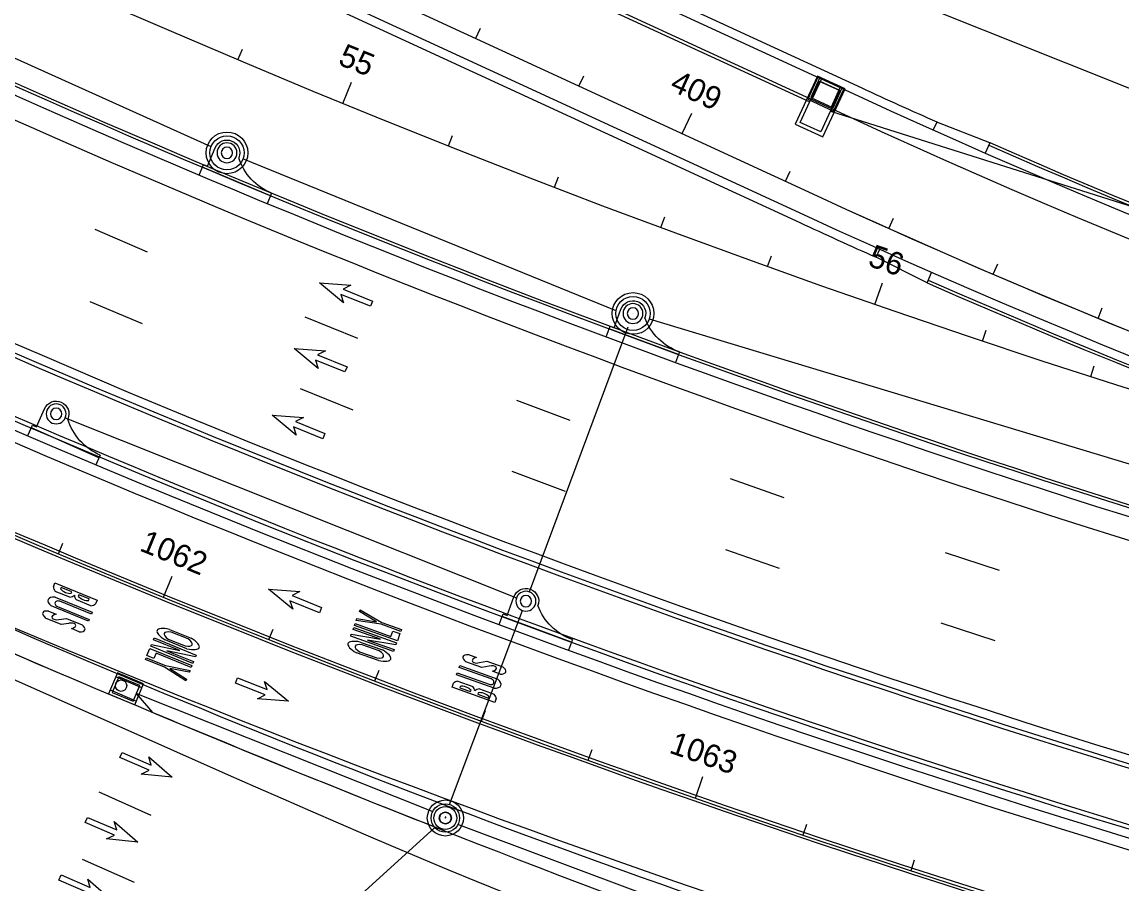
# Model space of a CAD drawing. Extents: x 468143 to 491361, y 1438528 to 1468730.
# Drawn here: x 488398.6 to 488592, y 1466773.1 to 1466924.6 of the extents above; entities that cross this region are included whole.
import ezdxf

# ---------------------------------------------------------------- set-up
doc = ezdxf.new("R2010")
doc.units = 0
doc.layers.add('Default', color=7, linetype='Continuous')
doc.layers.add('Xreference_dp', color=7, linetype='Continuous')

# ---------------------------------------------------------------- blocks, each defined once
blk = doc.blocks.new('POINT_DISPLAY')
at = {"layer": 'Default'}
blk.add_line((0, 0), (0, 0), dxfattribs=at)
blk = doc.blocks.new('InltCurb1_35')
at = {"layer": 'Default'}
for p, q in [((2.25, 2), (2.25, 5.5)), ((-10, 2), (-10, 0)), ((3, 2), (2.25, 2)), ((3, 0), (3, 2)), ((-10, 1.5), (3, 1.5))]:
    blk.add_line(p, q, dxfattribs=at)
for radius in [1.75, 1]:
    blk.add_circle((0, 5.5), radius, dxfattribs=at)
for centre, radius, start, end in [((0, 5.5), 2.25, 0, 180), ((-9.85, 12), 10, 269.1432, 319.4677)]:
    blk.add_arc(centre, radius, start, end, dxfattribs=at)
for p in [(0, 7.75), (-1.6, 6.2), (-1.22, 6.76), (-0.66, 7.12), (0, 7.25), (0, 7.25), (0.7, 7.1), (1.26, 6.72), (1.62, 6.16), (-1.75, 5.5), (-1.75, 5.5), (-1.62, 4.84), (-1.26, 4.28), (-0.7, 3.9), (0, 5.5), (0, 5.5), (0.66, 3.88), (1.22, 4.24), (1.6, 4.8), (1.75, 5.5), (1.75, 5.5), (0, 3.75), (0, 3.75), (0, 0), (0, 0)]:
    blk.add_blockref('POINT_DISPLAY', p, dxfattribs=at)
blk = doc.blocks.new('MHCover2')
at = {"layer": 'Default'}
for radius in [2, 1.06, 1]:
    blk.add_circle((0, 0), radius, dxfattribs=at)
for p in [(0, 2.5), (0, 2), (0, 2), (-2, 0), (-2, 0), (-1.83, 0.81), (-1.39, 1.43), (-0.75, 1.85), (0, 0), (0, 0), (0, 0), (0.81, 1.83), (1.43, 1.39), (1.85, 0.75), (2, 0), (2, 0), (-1.85, -0.75), (-1.43, -1.39), (-0.81, -1.83), (0.75, -1.85), (1.39, -1.43), (1.83, -0.81), (0, -2), (0, -2), (0, -2.5)]:
    blk.add_blockref('POINT_DISPLAY', p, dxfattribs=at)
blk = doc.blocks.new('InltCurb7_40')
at = {"layer": 'Default'}
for p, q in [((2.5, 4), (-2.5, 4)), ((-2.5, 4), (-2.5, 0)), ((2.5, 0), (2.5, 4)), ((2.5, 3.25), (-2.5, 3.25)), ((-2.5, 0.75), (2.5, 0.75)), ((-2.5, 0), (2.5, 0))]:
    blk.add_line(p, q, dxfattribs=at)
blk.add_lwpolyline([(-2, 0.5), (2, 0.5), (2, 3.5), (-2, 3.5)], close=True, dxfattribs=at)
blk.add_circle((-1.04, 2.19), 1, dxfattribs=at)
for p in [(0, 4), (-2, 3.5), (-2, 2), (-2, 2), (0, 3.5), (0, 3.5), (0, 2), (0, 2), (2, 3.5), (2, 2), (2, 2), (-2, 0.5), (0, 0.5), (0, 0.5), (0, 0), (0, 0), (2, 0.5)]:
    blk.add_blockref('POINT_DISPLAY', p, dxfattribs=at)
blk = doc.blocks.new('JBottom50Dia')
at = {"layer": 'Default'}
for radius in [3.17, 2.5, 2.5]:
    blk.add_circle((0, 0), radius, dxfattribs=at)
for p in [(-0.94, 2.32), (0, 2.5), (0, 2.5), (0, 2.5), (1.01, 2.29), (-2.29, 1.01), (-1.74, 1.79), (0, 0), (0, 0), (0, 0), (1.79, 1.74), (2.32, 0.94), (2.5, 0), (2.5, 0), (-2.5, 0), (-2.5, 0), (-2.32, -0.94), (-1.79, -1.74), (1.74, -1.79), (2.29, -1.01), (-1.01, -2.29), (0, -2.5), (0, -2.5), (0, -2.5), (0.94, -2.32)]:
    blk.add_blockref('POINT_DISPLAY', p, dxfattribs=at)
blk = doc.blocks.new('JBottom60Dia')
at = {"layer": 'Default'}
for radius in [3.67, 3, 3]:
    blk.add_circle((0, 0), radius, dxfattribs=at)
for p in [(-2.09, 2.15), (-1.13, 2.78), (0, 3), (0, 3), (0, 3), (1.21, 2.75), (2.15, 2.09), (-2.75, 1.21), (0, 0), (0, 0), (0, 0), (2.78, 1.13), (3, 0), (3, 0), (-3, 0), (-3, 0), (-2.78, -1.13), (2.75, -1.21), (-2.15, -2.09), (-1.21, -2.75), (0, -3), (0, -3), (0, -3), (1.13, -2.78), (2.09, -2.15)]:
    blk.add_blockref('POINT_DISPLAY', p, dxfattribs=at)
blk = doc.blocks.new('JBottom40x80')
at = {"layer": 'Default'}
for p, q in [((2.67, 4.67), (-2.67, 4.67)), ((-2.67, 4.67), (-2.67, -4.67)), ((-2, -4), (-2, 4)), ((-2, 4), (2, 4)), ((2, 4), (2, -4)), ((2.67, -4.67), (2.67, 4.67)), ((-2.67, -4.67), (2.67, -4.67)), ((2, -4), (-2, -4))]:
    blk.add_line(p, q, dxfattribs=at)
for p in [(-2, 4), (0, 4), (0, 4), (0, 4), (2, 4), (-2, 0), (-2, 0), (0, 0), (0, 0), (0, 0), (2, 0), (2, 0), (-2, -4), (0, -4), (0, -4), (0, -4), (2, -4)]:
    blk.add_blockref('POINT_DISPLAY', p, dxfattribs=at)
blk = doc.blocks.new('DAMerge_2')
at = {"layer": 'Default'}
blk.add_lwpolyline([(0.71, -4.09), (0, -3.39), (3.95, 0.56), (2.42, 0.68), (7.31, 3.21), (4.77, -1.68), (4.66, -0.15), (0.71, -4.09)], dxfattribs=at)
blk = doc.blocks.new('BUS_7')
at = {"layer": 'Default'}
for p, q in [((0, 2.46), (0, 3.17)), ((0, 3.17), (8, 3.17)), ((3.33, 2.83), (1.33, 2.83)), ((1.33, 2.83), (1.33, 2.58)), ((3.33, 2.58), (3.33, 2.83)), ((6.67, 2.83), (4.67, 2.83)), ((4.67, 2.83), (4.67, 2.58)), ((6.67, 2.58), (6.67, 2.83)), ((8, 3.17), (8, 2.46)), ((3.38, 1.83), (0.62, 1.83)), ((0.97, 0.86), (8, 0.86)), ((8, 0.5), (2, 0.5)), ((7.38, 1.83), (4.62, 1.83)), ((8, 0.86), (8, 0.5)), ((0.8, -1.83), (2.26, -1.83)), ((8, -0.83), (0.89, -0.83)), ((2, -0.5), (8, -0.5)), ((3.08, -2.5), (4.23, -1.83)), ((4.23, -1.83), (7.2, -1.83)), ((8, -0.5), (8, -0.83)), ((3.77, -3.17), (0.8, -3.17)), ((4.93, -2.5), (3.77, -3.17)), ((7.2, -3.17), (5.74, -3.17))]:
    blk.add_line(p, q, dxfattribs=at)
for centre, major_axis, ratio, start_param, end_param in [((2, 2.83), (-2.08, 0), 0.64, 0.283794, 0.848062), ((2.33, 2.83), (-1.17, 0), 0.428571, 0.5411, 2.600493), ((2, 2.83), (-2.08, 0), 0.64, 2.293531, 2.857799), ((6, 2.83), (2.08, 0), 0.64, 3.425387, 3.989655), ((5.67, 2.83), (1.17, 0), 0.428571, 3.682692, 5.742086), ((6, 2.83), (2.08, 0), 0.64, 5.435123, 5.999391), ((2, 0), (2, 0), 0.5, 2.110653, 4.126703), ((2, 0), (0.667, 0), 0.75, 1.570796, 4.712389), ((2, -2.5), (-2, 0), 0.416667, 5.35589, 7.210481), ((2.67, -2.17), (-0.877, -0.48), 0.5, 4.914869, 8.056461), ((6, -2.5), (2, 0), 0.416667, 5.35589, 7.210481), ((5.33, -2.83), (-0.869, -0.495), 0.5, 1.760499, 4.902092)]:
    blk.add_ellipse(centre, major_axis=major_axis, ratio=ratio, start_param=start_param, end_param=end_param, dxfattribs=at)
blk = doc.blocks.new('BikeONLY_2')
at = {"layer": 'Default'}
for p, q in [((0.97, 1.833), (3.03, 1.833)), ((2.8, 1.667), (1.2, 1.667)), ((1.2, 1), (2.8, 1)), ((3.03, 0.833), (0.97, 0.833))]:
    blk.add_line(p, q, dxfattribs=at)
for points in [[(0, -0.167), (0, 0), (2.5, 0.458), (0, 0.458), (0, 0.625), (4, 0.625), (4, 0.458), (1.45, 0), (4, 0), (4, -0.167), (0, -0.167)], [(0.667, -1.042), (0, -1.042), (0, -0.375), (4, -0.375), (4, -0.542), (0.667, -0.542), (0.667, -1.042)], [(4, -1.833), (1.833, -1.417), (0, -1.417), (0, -1.25), (1.833, -1.25), (4, -0.833), (4, -1.003), (2.283, -1.333), (4, -1.664), (4, -1.833)]]:
    blk.add_lwpolyline(points, dxfattribs=at)
for major_axis, ratio, start_param, end_param in [((2, 0), 0.291667, 2.111896, 4.171289), ((1.333, 0), 0.3125, 2.214297, 4.068888), ((1.333, 0), 0.3125, 5.35589, 7.210481), ((2, 0), 0.291667, 5.253489, 7.312882)]:
    blk.add_ellipse((2, 1.333), major_axis=major_axis, ratio=ratio, start_param=start_param, end_param=end_param, dxfattribs=at)
blk = doc.blocks.new('DAMerge_6')
at = {"layer": 'Default'}
blk.add_lwpolyline([(0.71, -4.09), (0, -3.39), (3.95, 0.56), (2.42, 0.68), (7.31, 3.21), (4.77, -1.68), (4.66, -0.15), (0.71, -4.09)], dxfattribs=at)
blk = doc.blocks.new('BUS_8')
at = {"layer": 'Default'}
for p, q in [((0, 2.46), (0, 3.17)), ((0, 3.17), (8, 3.17)), ((3.33, 2.83), (1.33, 2.83)), ((1.33, 2.83), (1.33, 2.58)), ((3.33, 2.58), (3.33, 2.83)), ((6.67, 2.83), (4.67, 2.83)), ((4.67, 2.83), (4.67, 2.58)), ((6.67, 2.58), (6.67, 2.83)), ((8, 3.17), (8, 2.46)), ((3.38, 1.83), (0.62, 1.83)), ((0.97, 0.86), (8, 0.86)), ((8, 0.5), (2, 0.5)), ((7.38, 1.83), (4.62, 1.83)), ((8, 0.86), (8, 0.5)), ((0.8, -1.83), (2.26, -1.83)), ((8, -0.83), (0.89, -0.83)), ((2, -0.5), (8, -0.5)), ((3.08, -2.5), (4.23, -1.83)), ((4.23, -1.83), (7.2, -1.83)), ((8, -0.5), (8, -0.83)), ((3.77, -3.17), (0.8, -3.17)), ((4.93, -2.5), (3.77, -3.17)), ((7.2, -3.17), (5.74, -3.17))]:
    blk.add_line(p, q, dxfattribs=at)
for centre, major_axis, ratio, start_param, end_param in [((2, 2.83), (-2.08, 0), 0.64, 0.283794, 0.848062), ((2.33, 2.83), (-1.17, 0), 0.428571, 0.5411, 2.600493), ((2, 2.83), (-2.08, 0), 0.64, 2.293531, 2.857799), ((6, 2.83), (2.08, 0), 0.64, 3.425387, 3.989655), ((5.67, 2.83), (1.17, 0), 0.428571, 3.682692, 5.742086), ((6, 2.83), (2.08, 0), 0.64, 5.435123, 5.999391), ((2, 0), (2, 0), 0.5, 2.110653, 4.126703), ((2, 0), (0.667, 0), 0.75, 1.570796, 4.712389), ((2, -2.5), (-2, 0), 0.416667, 5.35589, 7.210481), ((2.67, -2.17), (-0.877, -0.48), 0.5, 4.914869, 8.056461), ((6, -2.5), (2, 0), 0.416667, 5.35589, 7.210481), ((5.33, -2.83), (-0.869, -0.495), 0.5, 1.760499, 4.902092)]:
    blk.add_ellipse(centre, major_axis=major_axis, ratio=ratio, start_param=start_param, end_param=end_param, dxfattribs=at)
blk = doc.blocks.new('BikeONLY_4')
at = {"layer": 'Default'}
for p, q in [((0.97, 1.833), (3.03, 1.833)), ((2.8, 1.667), (1.2, 1.667)), ((1.2, 1), (2.8, 1)), ((3.03, 0.833), (0.97, 0.833))]:
    blk.add_line(p, q, dxfattribs=at)
for points in [[(0, -0.167), (0, 0), (2.5, 0.458), (0, 0.458), (0, 0.625), (4, 0.625), (4, 0.458), (1.45, 0), (4, 0), (4, -0.167), (0, -0.167)], [(0.667, -1.042), (0, -1.042), (0, -0.375), (4, -0.375), (4, -0.542), (0.667, -0.542), (0.667, -1.042)], [(4, -1.833), (1.833, -1.417), (0, -1.417), (0, -1.25), (1.833, -1.25), (4, -0.833), (4, -1.003), (2.283, -1.333), (4, -1.664), (4, -1.833)]]:
    blk.add_lwpolyline(points, dxfattribs=at)
for major_axis, ratio, start_param, end_param in [((2, 0), 0.291667, 2.111896, 4.171289), ((1.333, 0), 0.3125, 2.214297, 4.068888), ((1.333, 0), 0.3125, 5.35589, 7.210481), ((2, 0), 0.291667, 5.253489, 7.312882)]:
    blk.add_ellipse((2, 1.333), major_axis=major_axis, ratio=ratio, start_param=start_param, end_param=end_param, dxfattribs=at)

msp = doc.modelspace()

# ---------------------------------------------------------------- linework, layer by layer
at = {"layer": 'Xreference_dp'}
for p, q in [((488019.07, 1467150.3), (488543.93, 1466907.95)), ((488033.37, 1467149.8), (488546.25, 1466912.98)), ((488041.18, 1467144.49), (488545.6, 1466911.58)), ((488012.78, 1467136.68), (488537.64, 1466894.33)), ((488012.78, 1467136.68), (488537.64, 1466894.33)), ((488009.46, 1467132.11), (488535.31, 1466889.3)), ((488031.54, 1467123.61), (488535.96, 1466890.7)), ((488242.06, 1467053.44), (488807.02, 1466827.42)), ((488444.48, 1466953.32), (488537.08, 1466910.56)), ((488431.83, 1466902.65), (488371.12, 1466929.95)), ((488478.35, 1466921.71), (488479.19, 1466923.52)), ((488436.55, 1466917.95), (488437.33, 1466919.79)), ((488455.01, 1466910.26), (488456.53, 1466913.97)), ((488496.51, 1466913.32), (488497.34, 1466915.14)), ((488538.52, 1466914.85), (488536.73, 1466910.99)), ((488538.82, 1466914.71), (488537.25, 1466911.31)), ((488539.12, 1466914.57), (488537.55, 1466911.17)), ((488543.06, 1466912.76), (488538.52, 1466914.85)), ((488542.24, 1466912.58), (488538.91, 1466914.12)), ((488540.88, 1466909.63), (488542.45, 1466913.04)), ((488541.18, 1466909.49), (488542.75, 1466912.9)), ((488541.27, 1466908.9), (488543.06, 1466912.76)), ((488536.73, 1466910.99), (488541.27, 1466908.9)), ((488537.25, 1466911.31), (488541.18, 1466909.49)), ((488514.66, 1466904.94), (488516.34, 1466908.57)), ((488540.71, 1466908.88), (488659.38, 1466871.35)), ((488559.41, 1466906.99), (488558.77, 1466905.59)), ((488568.74, 1466903.35), (488559.41, 1466906.99)), ((488473.56, 1466902.78), (488474.3, 1466904.64)), ((488568.74, 1466903.35), (488567.93, 1466901.52)), ((488503.05, 1466873.8), (488437.43, 1466900.49)), ((488532.82, 1466896.56), (488533.66, 1466898.37)), ((488492.19, 1466895.51), (488492.91, 1466897.37)), ((488510.9, 1466888.43), (488511.6, 1466890.31)), ((488551.01, 1466888.25), (488551.83, 1466890.07)), ((488420.66, 1466884.12), (488411.47, 1466888.05)), ((488529.68, 1466881.57), (488530.36, 1466883.45)), ((488548.75, 1466883.19), (488549.39, 1466884.59)), ((488557.7, 1466878.71), (488548.75, 1466883.19)), ((488569.33, 1466880.21), (488570.12, 1466882.05)), ((488557.7, 1466878.71), (488558.5, 1466880.54)), ((488548.54, 1466874.91), (488549.85, 1466878.69)), ((488419.79, 1466871.46), (488410.58, 1466875.37)), ((488587.76, 1466872.45), (488588.52, 1466874.3)), ((488457.65, 1466868.9), (488448.37, 1466872.63)), ((488508.85, 1466872.34), (488724.74, 1466807.16)), ((488487.79, 1466824.33), (488505.14, 1466870.96)), ((488567.47, 1466868.46), (488568.11, 1466870.36)), ((488586.48, 1466862.22), (488587.09, 1466864.12)), ((488456.81, 1466856.32), (488447.53, 1466860.03)), ((488494.96, 1466854.48), (488485.6, 1466858.01)), ((488406.2, 1466854.93), (488485.54, 1466823.3)), ((488494.15, 1466841.97), (488484.79, 1466845.48)), ((488532.57, 1466840.86), (488523.14, 1466844.19)), ((488404.98, 1466831.04), (488405.75, 1466832.89)), ((488531.79, 1466828.43), (488522.35, 1466831.74)), ((488570.47, 1466828.07), (488560.97, 1466831.19)), ((488423.46, 1466823.39), (488424.97, 1466827.09)), ((488473.73, 1466786.95), (488486.58, 1466821.05)), ((488442.01, 1466815.93), (488442.75, 1466817.79)), ((488569.7, 1466815.7), (488560.2, 1466818.8)), ((488390.75, 1466811.76), (488434.84, 1466792.16)), ((488460.65, 1466808.67), (488461.36, 1466810.53)), ((488418.74, 1466806.47), (488470.79, 1466785.7)), ((488421.59, 1466803.11), (488418.74, 1466806.47)), ((488419.75, 1466803.91), (488419.74, 1466803.89)), ((488479.36, 1466801.6), (488480.05, 1466803.47)), ((488498.14, 1466794.72), (488498.82, 1466796.61)), ((488516.99, 1466788.05), (488518.31, 1466791.83)), ((488412.1, 1466789.13), (488421.24, 1466785.07)), ((488473.02, 1466784.55), (488473, 1466784.64)), ((488473.02, 1466784.55), (488473.08, 1466784.61)), ((488473.02, 1466784.55), (488473.04, 1466784.6)), ((488473.05, 1466784.62), (488473.07, 1466784.63)), ((488473.08, 1466784.67), (488473.06, 1466784.73)), ((488473.08, 1466784.78), (488473.09, 1466784.78)), ((488473.11, 1466784.8), (488473.12, 1466784.82)), ((488436.39, 1466751.31), (488471.15, 1466782.89)), ((488508.88, 1466770.79), (488475.24, 1466783.41)), ((488535.91, 1466781.57), (488536.55, 1466783.47)), ((488409.16, 1466777.31), (488418.3, 1466773.24)), ((488554.9, 1466775.29), (488555.52, 1466777.19))]:
    msp.add_line(p, q, dxfattribs=at)
for centre, radius, start, end in [((489145.02, 1468591.69), 1909.86, 245.36712, 306.9274), ((489143.9, 1468591.41), 1816.82, 245.36787, 299.96455), ((489145.02, 1468591.69), 1836.86, 245.36712, 266.14562), ((489145.02, 1468591.69), 1838.86, 245.36712, 266.14562), ((489145.02, 1468591.69), 1837.36, 245.36712, 266.14562), ((489145.02, 1468591.69), 1842.86, 245.36712, 265.63392), ((489082.61, 1468074.59), 1279.46, 245.21533, 245.86292), ((489082.61, 1468074.59), 1281, 245.21533, 263.11752), ((489082.61, 1468074.59), 1285, 245.21533, 263.11752), ((489082.61, 1468074.59), 1279.5, 246.31089, 259.7437), ((489082.61, 1468074.59), 1279, 246.31091, 259.7437), ((489082.61, 1468074.59), 1300, 245.21533, 263.11752), ((489082.61, 1468074.59), 1300, 245.21533, 263.22981), ((489082.61, 1468074.59), 1304, 245.21533, 263.11752), ((489082.61, 1468074.59), 1305.54, 245.21533, 245.86307), ((489145.02, 1468591.69), 1878.86, 245.36712, 266.78234), ((489145.02, 1468591.69), 1878.86, 245.36712, 266.78234), ((489145.02, 1468591.69), 1881.11, 245.36712, 266.78234), ((489145.02, 1468591.69), 1880.36, 245.36712, 266.78234), ((489082.61, 1468074.59), 1305.5, 246.30178, 263.11752), ((489082.61, 1468074.59), 1306, 246.30176, 263.11752), ((489145.02, 1468591.69), 1891.36, 245.36712, 267.59092), ((489145.02, 1468591.69), 1890.61, 245.36712, 263.85174), ((489145.02, 1468591.69), 1892.86, 245.36712, 267.59092), ((489145.02, 1468591.69), 1894.86, 245.36712, 267.58634), ((489145.02, 1468591.69), 1909.36, 245.36712, 267.72102), ((489145.02, 1468591.69), 1910.36, 245.37448, 267.72104), ((489412.39, 1469171.15), 2566.96, 246.02731, 251.49066), ((489201.99, 1468687.26), 2039.33, 245.90518, 247.12838), ((489095.84, 1468425.01), 1752.58, 246.02731, 253.56076), ((489145.02, 1468591.69), 1924.86, 246.95075, 267.69896), ((489430.33, 1469215.32), 2614.63, 247.30627, 248.50494), ((489167.8, 1468440.54), 1804, 246.0273, 267.4233)]:
    msp.add_arc(centre, radius, start, end, dxfattribs=at)
for centre, major_axis, start_param, end_param in [((488473.1, 1466784.57), (-0.0676, 0.0252), 5.759586, 6.283185), ((488473.13, 1466784.73), (0.0676, -0.0252), 2.617994, 3.665191), ((488473.02, 1466784.67), (-0.0676, 0.0252), 2.617994, 3.665191), ((488473.04, 1466784.83), (0.0676, -0.0252), 5.759586, 6.283185)]:
    msp.add_ellipse(centre, major_axis=major_axis, ratio=0.666667, start_param=start_param, end_param=end_param, dxfattribs=at)

# ---------------------------------------------------------------- block references
for name, p, rotation in [('JBottom40x80', (488538.9, 1466909.72), -24.784665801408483), ('POINT_DISPLAY', (488538.91, 1466914.12), -24.784665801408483), ('POINT_DISPLAY', (488538.23, 1466912.64), -24.784665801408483), ('POINT_DISPLAY', (488538.23, 1466912.64), -24.784665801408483), ('POINT_DISPLAY', (488539.89, 1466911.88), -24.784665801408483), ('POINT_DISPLAY', (488539.89, 1466911.88), -24.784665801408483), ('POINT_DISPLAY', (488540.58, 1466913.35), -24.784665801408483), ('POINT_DISPLAY', (488540.58, 1466913.35), -24.784665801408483), ('POINT_DISPLAY', (488540.79, 1466913.81), -24.784665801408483), ('POINT_DISPLAY', (488540.79, 1466913.81), -24.784665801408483), ('POINT_DISPLAY', (488542.24, 1466912.58), -24.784665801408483), ('POINT_DISPLAY', (488537.55, 1466911.17), -24.784665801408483), ('POINT_DISPLAY', (488539, 1466909.95), -24.784665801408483), ('POINT_DISPLAY', (488539.21, 1466910.4), -24.784665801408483), ('POINT_DISPLAY', (488539.21, 1466910.4), -24.784665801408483), ('POINT_DISPLAY', (488541.56, 1466911.11), -24.784665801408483), ('POINT_DISPLAY', (488541.56, 1466911.11), -24.784665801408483), ('POINT_DISPLAY', (488540.88, 1466909.63), -24.784665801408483), ('JBottom60Dia', (488434.63, 1466901.56), 75.32156597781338), ('DAMerge_2', (488456.71, 1466873.24), 112.97543337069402), ('DAMerge_6', (488456.71, 1466873.24), 112.97543337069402), ('JBottom60Dia', (488506.01, 1466873.31), 75.32156597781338), ('DAMerge_2', (488452.25, 1466861.69), 112.97543337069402), ('DAMerge_6', (488452.25, 1466861.69), 112.97543337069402), ('DAMerge_2', (488448.37, 1466849.95), 112.97543337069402), ('DAMerge_6', (488448.37, 1466849.95), 112.97543337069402), ('DAMerge_2', (488447.76, 1466819.34), 112.97543337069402), ('DAMerge_6', (488447.76, 1466819.34), 112.97543337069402), ('BUS_7', (488403.18, 1466822.96), -22.066060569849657), ('BUS_8', (488403.18, 1466822.96), -22.066060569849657), ('BUS_7', (488482.8, 1466807.87), 160.26941088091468), ('BUS_8', (488482.8, 1466807.87), 160.26941088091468), ('DAMerge_2', (488439.61, 1466810.54), -66.57436964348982), ('DAMerge_6', (488439.61, 1466810.54), -66.57436964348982), ('InltCurb7_40', (488416.12, 1466805.41), -22.865145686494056), ('DAMerge_2', (488419.35, 1466797.33), -68.47249683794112), ('DAMerge_6', (488419.35, 1466797.33), -68.47249683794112), ('DAMerge_2', (488413.27, 1466785.91), -68.47249683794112), ('DAMerge_6', (488413.27, 1466785.91), -68.47249683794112), ('JBottom50Dia', (488473.02, 1466784.55), 86.55174435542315), ('MHCover2', (488473.02, 1466784.55), -14.95217725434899), ('DAMerge_2', (488408.63, 1466775.79), -68.47249683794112), ('DAMerge_6', (488408.63, 1466775.79), -68.47249683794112)]:
    msp.add_blockref(name, p, dxfattribs=dict(at, rotation=rotation))
at = {"layer": 'Xreference_dp', "yscale": -1.0000000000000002}
for p, rotation in [((488432.49, 1466896.5), 157.15492878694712), ((488504.1, 1466868.14), 159.75351036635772), ((488402.37, 1466850.61), 156.1362180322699), ((488485.28, 1466817.53), 159.75351036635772)]:
    msp.add_blockref('InltCurb1_35', p, dxfattribs=dict(at, rotation=rotation))
at = {"layer": 'Xreference_dp'}
for name, p, xscale, yscale, rotation in [('BikeONLY_2', (488464.33, 1466815.03), 2, 1.9999999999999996, 160.26941088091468), ('BikeONLY_4', (488464.33, 1466815.03), 2, 1.9999999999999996, 160.26941088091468), ('BikeONLY_2', (488421.34, 1466815.06), 1.9999999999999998, 2.0000000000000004, -22.066060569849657), ('BikeONLY_4', (488421.34, 1466815.06), 1.9999999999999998, 2.0000000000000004, -22.066060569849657)]:
    msp.add_blockref(name, p, dxfattribs=dict(at, xscale=xscale, yscale=yscale, rotation=rotation))

# ---------------------------------------------------------------- texts
for s, rotation, p in [('55', 337.7175, (488453.97, 1466917.18)), ('409', 335.2153, (488512.29, 1466912.65)), ('56', 340.8711, (488547.12, 1466881.76)), ('1062', 337.8017, (488419.07, 1466831.66)), ('1063', 340.8017, (488512.18, 1466796.08))]:
    msp.add_text(s, height=4, rotation=rotation, dxfattribs=at).set_placement(p)

doc.saveas('drawing.dxf')
